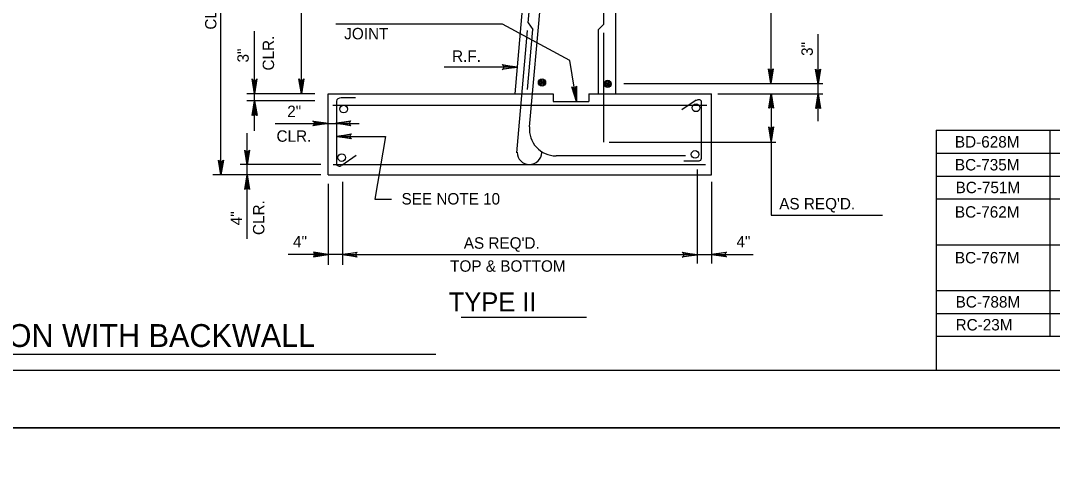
# Model space of a CAD drawing. Extents: x 235 to 2276, y 116 to 1308.
# Drawn here: x 807.5 to 1078.3, y 702.9 to 817.2 of the extents above; entities that cross this region are included whole.
import ezdxf

# ---------------------------------------------------------------- set-up
doc = ezdxf.new("R2010")
doc.units = 0
doc.layers.add('1', color=7, linetype='Continuous')
doc.layers.add('PLT-BNDY', color=7, linetype='Continuous')

msp = doc.modelspace()

# ---------------------------------------------------------------- linework, layer by layer
at = {"layer": '1'}
for p, q in [((860.12, 776.74), (860.12, 915.96)), ((963.72, 797.99), (963.72, 915.02)), ((1004.5, 800.65), (1004.5, 912.21)), ((881.22, 797.99), (881.22, 907.37)), ((940.75, 816.59), (948.09, 899.09)), ((937.31, 797.99), (945.28, 889.87)), ((960.59, 816.24), (960.59, 856.93)), ((941.1, 789.33), (944.23, 824.4)), ((934.03, 816.27), (890.24, 816.27)), ((951.69, 806.74), (934.03, 816.27)), ((940.75, 816.59), (942, 814.87)), ((959.22, 814.87), (960.59, 816.24)), ((868.93, 797.99), (868.93, 814.44)), ((937.78, 782.52), (940.59, 814.55)), ((940.59, 799.09), (942, 814.87)), ((959.22, 797.99), (959.22, 814.87)), ((960.59, 785.34), (960.59, 814.01)), ((1016.84, 800.65), (1016.84, 813.59)), ((918.71, 805.02), (937.94, 805.02)), ((953.44, 795.96), (951.69, 806.74)), ((965.85, 800.65), (1018.09, 800.65)), ((1016.82, 790.84), (1016.82, 800.65)), ((884.78, 797.99), (866.95, 797.99)), ((868.93, 788.3), (868.93, 797.99)), ((888.25, 776.74), (888.25, 797.99)), ((888.25, 797.99), (947.31, 797.99)), ((895.44, 796.9), (891.69, 796.9)), ((947.31, 797.99), (947.31, 795.96)), ((956.69, 797.99), (988.87, 797.99)), ((956.69, 797.99), (956.69, 795.96)), ((984.81, 796.27), (981.06, 793.77)), ((988.87, 776.74), (988.87, 797.99)), ((990.5, 797.99), (1018.09, 797.99)), ((1004.5, 797.99), (1004.5, 785.34)), ((884.78, 796.12), (866.95, 796.12)), ((889.5, 795.01), (987.62, 795.01)), ((890.44, 795.96), (890.44, 779.55)), ((947.31, 795.96), (956.69, 795.96)), ((986.22, 781.06), (986.22, 795.8)), ((874.35, 790.22), (888.25, 790.22)), ((888.25, 790.22), (896.43, 790.22)), ((1047.86, 788.41), (1047.86, 725.41)), ((1047.86, 788.41), (1205.42, 788.41)), ((1077.73, 734.41), (1077.73, 788.41)), ((867, 779.4), (867, 787.68)), ((890.44, 786.82), (903.31, 786.82)), ((903.31, 786.82), (900.49, 770.38)), ((962, 785.34), (997.62, 785.34)), ((997.62, 785.34), (1005.75, 785.34)), ((1004.5, 785.34), (1004.5, 766.12)), ((891.84, 779.24), (895.59, 781.9)), ((982.06, 781.71), (948.07, 781.71)), ((981.64, 780.43), (985.59, 780.43)), ((1047.86, 782.41), (1205.42, 782.41)), ((878.09, 779.4), (865.12, 779.4)), ((867, 759.93), (867, 779.4)), ((886.37, 779.4), (878.09, 779.4)), ((889.6, 779.4), (987.27, 779.4)), ((985.12, 778.15), (985.12, 753.46)), ((878.09, 776.74), (857.94, 776.74)), ((886.37, 776.74), (878.09, 776.74)), ((888.25, 776.74), (988.87, 776.74)), ((892, 774.87), (892, 753.15)), ((988.87, 774.87), (988.87, 753.46)), ((1047.86, 776.41), (1205.42, 776.41)), ((888.25, 774.4), (888.25, 753.15)), ((900.49, 770.38), (904.87, 770.38)), ((1047.86, 770.41), (1205.42, 770.41)), ((1004.5, 766.12), (1033.75, 766.12)), ((1047.86, 758.41), (1205.42, 758.41)), ((892, 755.8), (877.75, 755.8)), ((892, 755.8), (985.12, 755.8)), ((985.12, 755.8), (999.83, 755.8)), ((1047.86, 746.41), (1205.42, 746.41)), ((923.2, 739.37), (956.03, 739.37)), ((1047.86, 740.41), (1205.42, 740.41)), ((1047.86, 734.41), (1205.42, 734.41)), ((744.38, 729.75), (916.51, 729.75)), ((1405.42, 725.41), (619.42, 725.41))]:
    msp.add_line(p, q, dxfattribs=at)
for points in [[(934.08, 805.49), (934.33, 805.24), (937.83, 804.99), (934.08, 805.49), (933.95, 805.62), (937.83, 804.99), (934.33, 804.87), (934.2, 804.49), (937.83, 804.99), (933.95, 804.37), (934.2, 804.49)], [(1004.96, 804.41), (1004.71, 804.16), (1004.46, 800.66), (1004.96, 804.41), (1005.09, 804.54), (1004.46, 800.66), (1004.34, 804.16), (1003.96, 804.29), (1004.46, 800.66), (1003.84, 804.54), (1003.96, 804.29)], [(1017.32, 804.32), (1017.07, 804.07), (1016.82, 800.57), (1017.32, 804.32), (1017.44, 804.45), (1016.82, 800.57), (1016.69, 804.07), (1016.32, 804.2), (1016.82, 800.57), (1016.19, 804.45), (1016.32, 804.2)], [(869.43, 801.74), (869.18, 801.49), (868.93, 797.99), (869.43, 801.74), (869.56, 801.87), (868.93, 797.99), (868.81, 801.49), (868.43, 801.62), (868.93, 797.99), (868.31, 801.87), (868.43, 801.62)], [(881.72, 801.74), (881.47, 801.49), (881.22, 797.99), (881.72, 801.74), (881.84, 801.87), (881.22, 797.99), (881.09, 801.49), (880.72, 801.62), (881.22, 797.99), (880.59, 801.87), (880.72, 801.62)], [(953.3, 799.77), (953.05, 799.58), (953.44, 795.96), (953.3, 799.77), (953.43, 799.98), (953.44, 795.96), (952.68, 799.52), (952.39, 799.61), (953.44, 795.96), (952.18, 799.78), (952.39, 799.61)], [(868.46, 792.41), (868.71, 792.54), (868.96, 796.16), (868.46, 792.41), (868.34, 792.29), (868.96, 796.16), (869.09, 792.54), (869.46, 792.41), (868.96, 796.16), (869.59, 792.29), (869.46, 792.41)], [(1004.04, 794.31), (1004.29, 794.44), (1004.54, 798.06), (1004.04, 794.31), (1003.92, 794.19), (1004.54, 798.06), (1004.67, 794.44), (1005.04, 794.31), (1004.54, 798.06), (1005.17, 794.19), (1005.04, 794.31)], [(1016.34, 794.24), (1016.59, 794.37), (1016.84, 797.99), (1016.34, 794.24), (1016.22, 794.12), (1016.84, 797.99), (1016.97, 794.37), (1017.34, 794.24), (1016.84, 797.99), (1017.47, 794.12), (1017.34, 794.24)], [(884.48, 790.71), (884.6, 790.46), (888.23, 790.21), (884.48, 790.71), (884.23, 790.84), (888.23, 790.21), (884.6, 790.09), (884.48, 789.84), (888.23, 790.21), (884.23, 789.59), (884.48, 789.84)], [(894.02, 789.74), (893.9, 789.99), (890.27, 790.24), (894.02, 789.74), (894.15, 789.61), (890.27, 790.24), (893.9, 790.36), (894.02, 790.74), (890.27, 790.24), (894.15, 790.86), (894.02, 790.74)], [(1004.99, 789.21), (1004.74, 788.96), (1004.49, 785.46), (1004.99, 789.21), (1005.12, 789.33), (1004.49, 785.46), (1004.37, 788.96), (1003.99, 789.08), (1004.49, 785.46), (1003.87, 789.33), (1003.99, 789.08)], [(894.19, 786.32), (894.06, 786.57), (890.44, 786.82), (894.19, 786.32), (894.31, 786.19), (890.44, 786.82), (894.06, 786.94), (894.19, 787.32), (890.44, 786.82), (894.31, 787.44), (894.19, 787.32)], [(867.49, 783.1), (867.24, 782.85), (866.99, 779.35), (867.49, 783.1), (867.61, 783.22), (866.99, 779.35), (866.86, 782.85), (866.49, 782.97), (866.99, 779.35), (866.36, 783.22), (866.49, 782.97)], [(860.62, 780.46), (860.37, 780.21), (860.12, 776.71), (860.62, 780.46), (860.75, 780.59), (860.12, 776.71), (860, 780.21), (859.62, 780.34), (860.12, 776.71), (859.5, 780.59), (859.62, 780.34)], [(866.51, 773.02), (866.76, 773.14), (867.01, 776.77), (866.51, 773.02), (866.39, 772.89), (867.01, 776.77), (867.14, 773.14), (867.51, 773.02), (867.01, 776.77), (867.64, 772.89), (867.51, 773.02)], [(884.53, 755.36), (884.65, 755.61), (888.28, 755.86), (884.53, 755.36), (884.4, 755.23), (888.28, 755.86), (884.65, 755.98), (884.53, 756.36), (888.28, 755.86), (884.4, 756.48), (884.53, 756.36)], [(895.71, 755.31), (895.59, 755.56), (891.96, 755.81), (895.71, 755.31), (895.84, 755.18), (891.96, 755.81), (895.59, 755.93), (895.71, 756.31), (891.96, 755.81), (895.84, 756.43), (895.71, 756.31)], [(981.32, 756.29), (981.57, 756.04), (985.07, 755.79), (981.32, 756.29), (981.19, 756.42), (985.07, 755.79), (981.57, 755.67), (981.44, 755.29), (985.07, 755.79), (981.19, 755.17), (981.44, 755.29)], [(992.65, 755.33), (992.53, 755.58), (988.9, 755.83), (992.65, 755.33), (992.78, 755.2), (988.9, 755.83), (992.53, 755.95), (992.65, 756.33), (988.9, 755.83), (992.78, 756.45), (992.65, 756.33)]]:
    msp.add_lwpolyline(points, dxfattribs=at)
for centre, radius in [((944.38, 800.93), 0.954), ((944.38, 800.93), 0.681), ((944.38, 800.93), 0.372), ((944.38, 800.93), 0.188), ((944.38, 800.93), 0.0805), ((961.6, 800.57), 0.954), ((961.6, 800.57), 0.681), ((961.6, 800.57), 0.372), ((961.6, 800.57), 0.188), ((961.6, 800.57), 0.0805), ((892.32, 793.97), 1.01), ((984.8, 794.31), 1.01), ((984.56, 782.08), 1.01), ((891.82, 781.26), 1.01)]:
    msp.add_circle(centre, radius, dxfattribs=at)
for centre, radius, start, end in [((948.07, 788.71), 7, 174.9079, 270), ((941.07, 782.64), 3.22, 180, 0), ((985.59, 781.06), 0.625, 270, 360)]:
    msp.add_arc(centre, radius, start, end, dxfattribs=at)
for centre, major_axis, ratio, start_param, end_param in [((891.7, 796.04), (-1.3, 0), 0.697544, 4.712389, 6.283185), ((985.46, 795.88), (-0.812, 0), 0.632693, 3.141593, 5.497787), ((891.22, 779.6), (0.812, 0), 0.697544, 3.141593, 5.497787)]:
    msp.add_ellipse(centre, major_axis=major_axis, ratio=ratio, start_param=start_param, end_param=end_param, dxfattribs=at)
at = {"layer": 'PLT-BNDY'}
for points in [[(579.42, 1304.41), (1420.42, 1304.41), (1420.42, 710.41), (579.42, 710.41)], [(579.42, 710.41), (1420.42, 710.41), (1420.42, 116.41), (579.42, 116.41)]]:
    msp.add_lwpolyline(points, close=True, dxfattribs=at)

# ---------------------------------------------------------------- texts
at = {"layer": '1'}
for s, height, rotation, p in [('CLASS A CEMENT CONCRETE', 2.97, 90, (858.92, 814.81)), ('CLR.', 3, 90, (874.06, 804.08)), ('3"', 3, 90, (867.41, 806.19)), ('3"', 3, 90, (1015.46, 807.91)), ('CLR.', 3, 90, (871.52, 760.94)), ('4"', 3, 90, (865.62, 763.51)), ('4"', 3.003, 360, (879.03, 757.72))]:
    msp.add_text(s, height=height, rotation=rotation, dxfattribs=at).set_placement(p)
for s, height, p in [('JOINT', 3, (892.47, 812.26)), ('R.F.', 3, (920.77, 806.36)), ('2"', 3.003, (877.51, 791.87)), ('CLR.', 3, (874.7, 785.4)), ('BD-628M', 3, (1052.75, 783.88)), ('BC-735M', 3, (1052.75, 777.88)), ('BC-751M', 3, (1052.93, 771.92)), ('SEE NOTE 10', 3, (907.51, 768.95)), ("AS REQ'D.", 3, (1006.64, 767.66)), ('BC-762M', 3, (1052.75, 765.5)), ("AS REQ'D.", 3, (923.85, 757.36)), ('4"', 3.003, (995.43, 757.72)), ('BC-767M', 3, (1052.75, 753.5)), ('TOP & BOTTOM', 3, (920.27, 751.32)), (' TYPE II', 5, (918.04, 740.9)), ('BC-788M', 3, (1052.93, 741.92)), ('TYPICAL SECTION WITH BACKWALL', 6, (744.85, 731.59)), ('RC-23M', 3, (1052.93, 735.92))]:
    msp.add_text(s, height=height, dxfattribs=at).set_placement(p)

doc.saveas('drawing.dxf')
